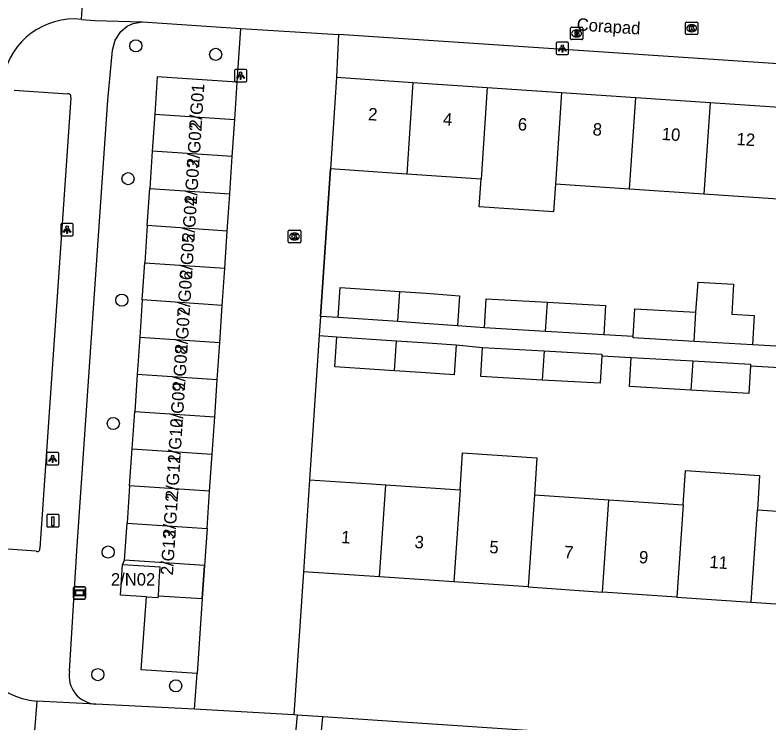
# Model space of a CAD drawing. Extents: x 161848 to 162726, y 385382 to 386521.
# Drawn here: x 162036.5 to 162097.2, y 385869.2 to 385926.3 of the extents above; entities that cross this region are included whole.
import ezdxf

# ---------------------------------------------------------------- set-up
doc = ezdxf.new("R2010")
doc.units = 0
for name, color, linetype in [('IMGEO_Boom', 7, 'Continuous'), ('IMGEO_Brandkraan', 7, 'Continuous'), ('IMGEO_Hek', 7, 'Continuous'), ('IMGEO_Kolk', 7, 'Continuous'), ('IMGEO_Laadpaal', 7, 'Continuous'), ('IMGEO_Lichtpunt', 7, 'Continuous'), ('IMGEO_Muur', 7, 'Continuous'), ('IMGEO_Openbare_ruimte_label', 7, 'Continuous'), ('IMGEO_Pand', 7, 'Continuous'), ('IMGEO_Pand_nummerreeks', 7, 'Continuous'), ('IMGEO_Parkeervlak_open', 7, 'Continuous'), ('IMGEO_Rijbaan_lokaal_open', 7, 'Continuous'), ('IMGEO_Verklikker', 7, 'Continuous'), ('IMGEO_Voetpad_open', 7, 'Continuous'), ('IMGEO_Woonerf_open', 7, 'Continuous')]:
    doc.layers.add(name, color=color, linetype=linetype)

msp = doc.modelspace()

# ---------------------------------------------------------------- linework, layer by layer
at = {"layer": 'IMGEO_Boom'}
for centre in [(162046.245, 385923.789), (162052.67, 385923.106), (162045.611, 385913.088), (162045.117, 385903.3), (162044.42, 385893.36), (162044.003, 385883.001), (162043.179, 385873.125), (162049.451, 385872.226)]:
    msp.add_circle(centre, 0.489, dxfattribs=at)
at = {"layer": 'IMGEO_Brandkraan'}
for p, q in [((162081.246, 385924.369), (162081.246, 385925.221)), ((162081.321, 385925.295), (162082.173, 385925.295)), ((162081.734, 385925.075), (162081.759, 385925.075)), ((162082.247, 385925.221), (162082.247, 385924.369)), ((162081.757, 385924.515), (162081.732, 385924.515)), ((162082.173, 385924.295), (162081.321, 385924.295))]:
    msp.add_line(p, q, dxfattribs=at)
for points in [[(162081.246, 385924.369), (162081.246, 385925.221)], [(162081.321, 385925.295), (162082.173, 385925.295)], [(162081.594, 385924.995), (162081.594, 385924.595), (162081.807, 385924.595)], [(162081.825, 385924.995), (162081.594, 385924.995)], [(162082.247, 385925.221), (162082.247, 385924.369)], [(162081.773, 385924.914), (162081.719, 385924.914), (162081.719, 385924.838)], [(162081.719, 385924.838), (162081.772, 385924.838)], [(162081.781, 385924.762), (162081.719, 385924.762), (162081.719, 385924.681)], [(162081.719, 385924.681), (162081.781, 385924.681)], [(162082.173, 385924.295), (162081.321, 385924.295)]]:
    msp.add_lwpolyline(points, dxfattribs=at)
for centre, radius, start, end in [((162081.323, 385925.219), 0.0765, 91.55205, 178.44795), ((162081.323, 385925.219), 0.0765, 91.55205, 178.44795), ((162081.829, 385924.85), 0.145, 59.4692, 91.53667), ((162082.171, 385925.219), 0.0765, 1.55205, 88.44795), ((162082.171, 385925.219), 0.0765, 1.55205, 88.44795), ((162081.774, 385924.876), 0.0379, 267.82845, 90.93552), ((162081.782, 385924.721), 0.0404, 269.87594, 90.50774), ((162081.813, 385924.846), 0.251, 268.66757, 293.53466), ((162081.854, 385924.897), 0.0922, 285.51372, 58.15012), ((162081.859, 385924.705), 0.105, 301.31148, 78.98903), ((162081.323, 385924.371), 0.0765, 181.55205, 268.44795), ((162081.323, 385924.371), 0.0765, 181.55205, 268.44795), ((162082.171, 385924.371), 0.0765, 271.55205, 358.44795), ((162082.171, 385924.371), 0.0765, 271.55205, 358.44795)]:
    msp.add_arc(centre, radius, start, end, dxfattribs=at)
for centre, major_axis, ratio, start_param, end_param in [((162081.733, 385924.795), (-0.387, 0.002), 0.722429, 4.712389, 7.853982), ((162081.758, 385924.795), (-0.39, 0.002), 0.717154, 1.570796, 4.712389)]:
    msp.add_ellipse(centre, major_axis=major_axis, ratio=ratio, start_param=start_param, end_param=end_param, dxfattribs=at)
at = {"layer": 'IMGEO_Hek'}
for points in [[(162051.593, 385879.249), (162051.781, 385881.906)], [(162048.052, 385879.467), (162051.593, 385879.249)]]:
    msp.add_lwpolyline(points, dxfattribs=at)
at = {"layer": 'IMGEO_Kolk'}
for p, q in [((162090.514, 385924.785), (162090.514, 385925.637)), ((162090.589, 385925.711), (162091.441, 385925.711)), ((162091.515, 385925.637), (162091.515, 385924.785)), ((162091.002, 385925.491), (162091.027, 385925.491)), ((162091.441, 385924.711), (162090.589, 385924.711)), ((162091.025, 385924.931), (162091, 385924.931)), ((162058.519, 385908.006), (162058.519, 385908.858)), ((162058.594, 385908.932), (162059.446, 385908.932)), ((162059.007, 385908.712), (162059.032, 385908.712)), ((162059.52, 385908.858), (162059.52, 385908.006)), ((162059.03, 385908.152), (162059.005, 385908.152)), ((162059.446, 385907.932), (162058.594, 385907.932))]:
    msp.add_line(p, q, dxfattribs=at)
for points in [[(162090.514, 385924.785), (162090.514, 385925.637)], [(162090.589, 385925.711), (162091.441, 385925.711)], [(162091.515, 385925.637), (162091.515, 385924.785)], [(162090.835, 385925.411), (162090.958, 385925.411), (162090.958, 385925.26), (162091.088, 385925.411), (162091.252, 385925.411), (162091.106, 385925.26), (162091.259, 385925.011), (162091.107, 385925.011), (162091.022, 385925.175), (162090.958, 385925.108), (162090.958, 385925.011), (162090.835, 385925.011), (162090.835, 385925.411)], [(162091.441, 385924.711), (162090.589, 385924.711)], [(162058.519, 385908.006), (162058.519, 385908.858)], [(162058.594, 385908.932), (162059.446, 385908.932)], [(162058.84, 385908.632), (162058.963, 385908.632), (162058.963, 385908.481), (162059.093, 385908.632), (162059.257, 385908.632), (162059.111, 385908.481), (162059.264, 385908.232), (162059.112, 385908.232), (162059.027, 385908.396), (162058.963, 385908.329), (162058.963, 385908.232), (162058.84, 385908.232), (162058.84, 385908.632)], [(162059.52, 385908.858), (162059.52, 385908.006)], [(162059.446, 385907.932), (162058.594, 385907.932)]]:
    msp.add_lwpolyline(points, dxfattribs=at)
for centre, start, end in [((162090.591, 385925.635), 91.55205, 178.44795), ((162090.591, 385925.635), 91.55205, 178.44795), ((162091.439, 385925.635), 1.55205, 88.44795), ((162091.439, 385925.635), 1.55205, 88.44795), ((162090.591, 385924.787), 181.55205, 268.44795), ((162090.591, 385924.787), 181.55205, 268.44795), ((162091.439, 385924.787), 271.55205, 358.44795), ((162091.439, 385924.787), 271.55205, 358.44795), ((162058.596, 385908.856), 91.55205, 178.44795), ((162058.596, 385908.856), 91.55205, 178.44795), ((162059.444, 385908.856), 1.55205, 88.44795), ((162059.444, 385908.856), 1.55205, 88.44795), ((162058.596, 385908.008), 181.55205, 268.44795), ((162058.596, 385908.008), 181.55205, 268.44795), ((162059.444, 385908.008), 271.55205, 358.44795), ((162059.444, 385908.008), 271.55205, 358.44795)]:
    msp.add_arc(centre, 0.0765, start, end, dxfattribs=at)
for centre, major_axis, ratio, start_param, end_param in [((162091.001, 385925.211), (-0.387, 0.002), 0.722429, 4.712389, 7.853982), ((162091.026, 385925.211), (-0.39, 0.002), 0.717154, 1.570796, 4.712389), ((162059.006, 385908.432), (-0.387, 0.002), 0.722429, 4.712389, 7.853982), ((162059.031, 385908.432), (-0.39, 0.002), 0.717154, 1.570796, 4.712389)]:
    msp.add_ellipse(centre, major_axis=major_axis, ratio=ratio, start_param=start_param, end_param=end_param, dxfattribs=at)
at = {"layer": 'IMGEO_Laadpaal'}
for p, q in [((162039.063, 385885.939), (162039.063, 385885.098)), ((162039.063, 385885.939), (162039.063, 385885.098)), ((162039.979, 385886.023), (162039.138, 385886.023)), ((162039.979, 385886.023), (162039.138, 385886.023)), ((162040.063, 385885.107), (162040.063, 385885.948)), ((162040.063, 385885.107), (162040.063, 385885.948)), ((162039.147, 385885.023), (162039.988, 385885.023)), ((162039.147, 385885.023), (162039.988, 385885.023))]:
    msp.add_line(p, q, dxfattribs=at)
msp.add_lwpolyline([(162039.478, 385885.836), (162039.638, 385885.836), (162039.638, 385885.103), (162039.478, 385885.103), (162039.478, 385885.836)], dxfattribs=at)
for centre, start, end in [((162039.141, 385885.945), 92.4484, 184.28452), ((162039.141, 385885.945), 92.4484, 184.28452), ((162039.985, 385885.945), 2.4484, 94.28452), ((162039.985, 385885.945), 2.4484, 94.28452), ((162039.141, 385885.101), 182.4484, 274.28452), ((162039.141, 385885.101), 182.4484, 274.28452), ((162039.985, 385885.101), 272.4484, 4.28452), ((162039.985, 385885.101), 272.4484, 4.28452)]:
    msp.add_arc(centre, 0.0779, start, end, dxfattribs=at)
at = {"layer": 'IMGEO_Lichtpunt'}
for p, q in [((162080.1, 385923.992), (162080.1, 385923.185)), ((162080.1, 385923.992), (162080.1, 385923.185)), ((162081.002, 385924.087), (162080.194, 385924.087)), ((162081.002, 385924.087), (162080.194, 385924.087)), ((162081.096, 385923.185), (162081.096, 385923.992)), ((162081.096, 385923.185), (162081.096, 385923.992)), ((162080.194, 385923.091), (162081.002, 385923.091)), ((162080.194, 385923.091), (162081.002, 385923.091)), ((162054.183, 385921.797), (162054.183, 385920.99)), ((162054.183, 385921.797), (162054.183, 385920.99)), ((162055.085, 385921.892), (162054.277, 385921.892)), ((162055.085, 385921.892), (162054.277, 385921.892)), ((162055.179, 385920.99), (162055.179, 385921.797)), ((162055.179, 385920.99), (162055.179, 385921.797)), ((162054.277, 385920.896), (162055.085, 385920.896)), ((162054.277, 385920.896), (162055.085, 385920.896)), ((162040.202, 385909.388), (162040.202, 385908.581)), ((162040.202, 385909.388), (162040.202, 385908.581)), ((162041.104, 385909.483), (162040.296, 385909.483)), ((162041.104, 385909.483), (162040.296, 385909.483)), ((162041.198, 385908.581), (162041.198, 385909.388)), ((162041.198, 385908.581), (162041.198, 385909.388)), ((162040.296, 385908.487), (162041.104, 385908.487)), ((162040.296, 385908.487), (162041.104, 385908.487)), ((162039.942, 385891.019), (162039.134, 385891.019)), ((162039.942, 385891.019), (162039.134, 385891.019)), ((162039.04, 385890.924), (162039.04, 385890.117)), ((162039.04, 385890.924), (162039.04, 385890.117)), ((162040.036, 385890.117), (162040.036, 385890.924)), ((162040.036, 385890.117), (162040.036, 385890.924)), ((162039.134, 385890.023), (162039.942, 385890.023)), ((162039.134, 385890.023), (162039.942, 385890.023))]:
    msp.add_line(p, q, dxfattribs=at)
for points in [[(162080.474, 385923.656), (162080.513, 385923.628), (162080.325, 385923.366), (162080.287, 385923.393), (162080.474, 385923.656)], [(162080.576, 385923.608), (162080.623, 385923.608), (162080.623, 385923.286), (162080.576, 385923.286), (162080.576, 385923.608)], [(162080.686, 385923.628), (162080.724, 385923.655), (162080.911, 385923.393), (162080.872, 385923.365), (162080.686, 385923.628)], [(162054.557, 385921.461), (162054.596, 385921.433), (162054.408, 385921.171), (162054.37, 385921.198), (162054.557, 385921.461)], [(162054.659, 385921.413), (162054.706, 385921.413), (162054.706, 385921.091), (162054.659, 385921.091), (162054.659, 385921.413)], [(162054.769, 385921.433), (162054.807, 385921.46), (162054.994, 385921.198), (162054.955, 385921.17), (162054.769, 385921.433)], [(162040.576, 385909.052), (162040.615, 385909.024), (162040.427, 385908.762), (162040.389, 385908.789), (162040.576, 385909.052)], [(162040.678, 385909.004), (162040.725, 385909.004), (162040.725, 385908.682), (162040.678, 385908.682), (162040.678, 385909.004)], [(162040.788, 385909.024), (162040.826, 385909.051), (162041.013, 385908.789), (162040.974, 385908.761), (162040.788, 385909.024)], [(162039.414, 385890.588), (162039.453, 385890.56), (162039.265, 385890.298), (162039.227, 385890.325), (162039.414, 385890.588)], [(162039.516, 385890.54), (162039.563, 385890.54), (162039.563, 385890.218), (162039.516, 385890.218), (162039.516, 385890.54)], [(162039.626, 385890.56), (162039.664, 385890.587), (162039.851, 385890.325), (162039.812, 385890.297), (162039.626, 385890.56)]]:
    msp.add_lwpolyline(points, dxfattribs=at)
for centre in [(162080.599, 385923.79), (162054.682, 385921.595), (162040.701, 385909.186), (162039.539, 385890.722)]:
    msp.add_circle(centre, 0.0994, dxfattribs=at)
for centre, start, end in [((162080.194, 385923.992), 90, 180), ((162080.194, 385923.992), 90, 180), ((162081.002, 385923.992), 0, 90), ((162081.002, 385923.992), 0, 90), ((162080.194, 385923.185), 180, 270), ((162080.194, 385923.185), 180, 270), ((162081.002, 385923.185), 270, 0), ((162081.002, 385923.185), 270, 360), ((162054.277, 385921.797), 90, 180), ((162054.277, 385921.797), 90, 180), ((162055.085, 385921.797), 0, 90), ((162055.085, 385921.797), 0, 90), ((162054.277, 385920.99), 180, 270), ((162054.277, 385920.99), 180, 270), ((162055.085, 385920.99), 270, 0), ((162055.085, 385920.99), 270, 360), ((162040.296, 385909.388), 90, 180), ((162040.296, 385909.388), 90, 180), ((162041.104, 385909.388), 0, 90), ((162041.104, 385909.388), 0, 90), ((162040.296, 385908.581), 180, 270), ((162040.296, 385908.581), 180, 270), ((162041.104, 385908.581), 270, 0), ((162041.104, 385908.581), 270, 360), ((162039.134, 385890.924), 90, 180), ((162039.134, 385890.924), 90, 180), ((162039.942, 385890.924), 0, 90), ((162039.942, 385890.924), 0, 90), ((162039.134, 385890.117), 180, 270), ((162039.134, 385890.117), 180, 270), ((162039.942, 385890.117), 270, 0), ((162039.942, 385890.117), 270, 360)]:
    msp.add_arc(centre, 0.0946, start, end, dxfattribs=at)
at = {"layer": 'IMGEO_Muur'}
for points in [[(162061.115, 385901.991), (162061.91, 385913.871)], [(162061.012, 385900.444), (162060.235, 385888.83)]]:
    msp.add_lwpolyline(points, dxfattribs=at)
at = {"layer": 'IMGEO_Pand'}
for points in [[(162054.41, 385920.859), (162047.964, 385921.294), (162047.762, 385918.298)], [(162054.208, 385917.863), (162054.41, 385920.859)], [(162062.409, 385921.268), (162061.91, 385913.871)], [(162062.409, 385921.268), (162068.56, 385920.853)], [(162068.56, 385920.853), (162068.06, 385913.456)], [(162068.56, 385920.853), (162074.547, 385920.449)], [(162074.547, 385920.449), (162074.047, 385913.052)], [(162074.547, 385920.449), (162080.533, 385920.045)], [(162080.533, 385920.045), (162080.033, 385912.648)], [(162080.533, 385920.045), (162086.52, 385919.641)], [(162086.02, 385912.244), (162086.52, 385919.641)], [(162086.52, 385919.641), (162092.506, 385919.236)], [(162092.506, 385919.236), (162092.006, 385911.84)], [(162092.506, 385919.236), (162098.492, 385918.832)], [(162047.762, 385918.298), (162047.56, 385915.301)], [(162047.762, 385918.298), (162054.208, 385917.863)], [(162054.006, 385914.866), (162054.208, 385917.863)], [(162047.56, 385915.301), (162047.357, 385912.305)], [(162054.006, 385914.866), (162047.56, 385915.301)], [(162053.803, 385911.87), (162054.006, 385914.866)], [(162068.06, 385913.456), (162066.899, 385913.534), (162061.91, 385913.871)], [(162074.047, 385913.052), (162068.06, 385913.456)], [(162080.033, 385912.648), (162079.884, 385910.429), (162073.897, 385910.834), (162074.047, 385913.052)], [(162047.155, 385909.309), (162047.357, 385912.305)], [(162047.357, 385912.305), (162053.803, 385911.87)], [(162086.02, 385912.244), (162080.033, 385912.648)], [(162092.006, 385911.84), (162086.02, 385912.244)], [(162053.601, 385908.873), (162053.803, 385911.87)], [(162097.992, 385911.436), (162092.006, 385911.84)], [(162047.155, 385909.309), (162046.953, 385906.312)], [(162053.601, 385908.873), (162047.155, 385909.309)], [(162053.399, 385905.877), (162053.601, 385908.873)], [(162046.751, 385903.316), (162046.953, 385906.312)], [(162046.953, 385906.312), (162053.399, 385905.877)], [(162053.197, 385902.881), (162053.399, 385905.877)], [(162091.363, 385902.329), (162091.527, 385904.756), (162094.38, 385904.595), (162094.243, 385902.166), (162096.053, 385902.064), (162095.92, 385899.71)], [(162062.543, 385901.895), (162062.706, 385904.319), (162067.507, 385903.995)], [(162067.343, 385901.571), (162067.507, 385903.995)], [(162067.507, 385903.995), (162069.631, 385903.852), (162072.304, 385903.662), (162072.138, 385901.245)], [(162046.751, 385903.316), (162046.548, 385900.319)], [(162053.197, 385902.881), (162046.751, 385903.316)], [(162074.33, 385901.063), (162074.463, 385903.417), (162079.39, 385903.138)], [(162079.231, 385900.785), (162079.39, 385903.138)], [(162079.39, 385903.138), (162084.08, 385902.873), (162083.947, 385900.519)], [(162052.994, 385899.884), (162053.197, 385902.881)], [(162086.31, 385900.385), (162086.436, 385902.608), (162091.363, 385902.329)], [(162091.204, 385899.976), (162091.363, 385902.329)], [(162067.343, 385901.571), (162062.543, 385901.895)], [(162072.138, 385901.245), (162069.465, 385901.428), (162067.343, 385901.571)], [(162079.231, 385900.785), (162074.33, 385901.063)], [(162083.947, 385900.519), (162079.231, 385900.785)], [(162046.548, 385900.319), (162046.346, 385897.323)], [(162046.548, 385900.319), (162052.994, 385899.884)], [(162067.075, 385897.61), (162062.271, 385897.934), (162062.434, 385900.348)], [(162062.434, 385900.348), (162067.238, 385900.023)], [(162091.204, 385899.976), (162086.303, 385900.254), (162086.31, 385900.385)], [(162052.792, 385896.888), (162052.994, 385899.884)], [(162067.075, 385897.61), (162067.238, 385900.023)], [(162072.034, 385899.699), (162071.871, 385897.286), (162069.196, 385897.467), (162067.075, 385897.61)], [(162067.238, 385900.023), (162069.36, 385899.88), (162072.034, 385899.699)], [(162078.974, 385896.864), (162074.039, 385897.143), (162074.172, 385899.497)], [(162074.172, 385899.497), (162079.132, 385899.216)], [(162095.92, 385899.71), (162091.204, 385899.976)], [(162079.132, 385899.216), (162078.974, 385896.864)], [(162079.132, 385899.216), (162083.789, 385898.953), (162083.782, 385898.822)], [(162083.782, 385898.822), (162083.656, 385896.599), (162078.974, 385896.864)], [(162090.947, 385896.055), (162086.012, 385896.334), (162086.145, 385898.688)], [(162086.145, 385898.688), (162091.106, 385898.407)], [(162091.106, 385898.407), (162090.947, 385896.055)], [(162091.106, 385898.407), (162095.762, 385898.144), (162095.755, 385898.014)], [(162095.755, 385898.014), (162095.629, 385895.79), (162090.947, 385896.055)], [(162046.346, 385897.323), (162046.144, 385894.327)], [(162052.792, 385896.888), (162046.346, 385897.323)], [(162052.59, 385893.892), (162052.792, 385896.888)], [(162045.942, 385891.33), (162046.144, 385894.327)], [(162046.144, 385894.327), (162052.59, 385893.892)], [(162052.388, 385890.895), (162052.59, 385893.892)], [(162045.739, 385888.334), (162045.942, 385891.33)], [(162045.942, 385891.33), (162052.388, 385890.895)], [(162072.363, 385888.013), (162072.565, 385891.006), (162078.551, 385890.602), (162078.349, 385887.609)], [(162052.185, 385887.899), (162052.388, 385890.895)], [(162090.322, 385886.799), (162090.507, 385889.565), (162096.492, 385889.161), (162096.308, 385886.395)], [(162060.235, 385888.83), (162059.734, 385881.408)], [(162060.235, 385888.83), (162065.224, 385888.493), (162066.376, 385888.417)], [(162045.739, 385888.334), (162045.537, 385885.337)], [(162052.185, 385887.899), (162045.739, 385888.334)], [(162065.875, 385880.994), (162066.376, 385888.417)], [(162066.376, 385888.417), (162072.363, 385888.013)], [(162072.363, 385888.013), (162071.862, 385880.59)], [(162051.983, 385884.902), (162052.185, 385887.899)], [(162078.349, 385887.609), (162077.848, 385880.186)], [(162078.349, 385887.609), (162084.336, 385887.204)], [(162083.835, 385879.781), (162084.336, 385887.204)], [(162084.336, 385887.204), (162090.322, 385886.799)], [(162090.322, 385886.799), (162089.821, 385879.377)], [(162095.807, 385878.973), (162096.308, 385886.395)], [(162096.308, 385886.395), (162102.295, 385885.991)], [(162045.335, 385882.341), (162045.537, 385885.337)], [(162045.537, 385885.337), (162051.983, 385884.902)], [(162051.983, 385884.902), (162051.781, 385881.906)], [(162047.093, 385879.396), (162045.014, 385879.525), (162045.166, 385881.962)], [(162048.052, 385879.467), (162048.153, 385881.095), (162048.195, 385881.774), (162045.166, 385881.962)], [(162051.781, 385881.906), (162045.335, 385882.341)], [(162065.875, 385880.994), (162059.734, 385881.408)], [(162071.862, 385880.59), (162065.875, 385880.994)], [(162077.848, 385880.186), (162071.862, 385880.59)], [(162077.848, 385880.186), (162083.835, 385879.781)], [(162047.093, 385879.396), (162048.044, 385879.337), (162048.052, 385879.467)], [(162089.821, 385879.377), (162083.835, 385879.781)], [(162089.821, 385879.377), (162095.807, 385878.973)], [(162095.807, 385878.973), (162101.794, 385878.569)]]:
    msp.add_lwpolyline(points, dxfattribs=at)
at = {"layer": 'IMGEO_Parkeervlak_open'}
msp.add_lwpolyline([(162051.166, 385873.202), (162046.678, 385873.52), (162047.093, 385879.396)], dxfattribs=at)
at = {"layer": 'IMGEO_Rijbaan_lokaal_open'}
for points in [[(162041.849, 385925.93), (162042.191, 385931.089)], [(162054.41, 385920.859), (162054.686, 385925.183)], [(162054.686, 385925.183), (162062.576, 385924.706)], [(162062.576, 385924.706), (162062.409, 385921.268)], [(162061.91, 385913.871), (162061.115, 385901.991)], [(162061.115, 385901.991), (162061.012, 385900.444)], [(162061.012, 385900.444), (162060.235, 385888.83)], [(162051.781, 385881.906), (162051.593, 385879.249)], [(162059.734, 385881.408), (162058.972, 385869.883)], [(162051.593, 385879.249), (162051.166, 385873.202)], [(162050.963, 385870.339), (162051.166, 385873.202)], [(162038.259, 385870.998), (162037.888, 385866.206)], [(162058.972, 385869.883), (162050.963, 385870.339)]]:
    msp.add_lwpolyline(points, dxfattribs=at)
for centre, radius, start, end in [((162041.277, 385920.133), 5.825, 84.36365, 168.49526), ((162038.751, 385877.016), 6.038, 177.64802, 265.3244)]:
    msp.add_arc(centre, radius, start, end, dxfattribs=at)
at = {"layer": 'IMGEO_Verklikker'}
for p, q in [((162041.204, 385879.312), (162041.204, 385880.112)), ((162041.204, 385880.112), (162041.204, 385879.312)), ((162041.304, 385880.212), (162042.094, 385880.212)), ((162042.094, 385880.212), (162041.304, 385880.212)), ((162042.194, 385880.112), (162042.194, 385879.312)), ((162042.194, 385879.312), (162042.194, 385880.112)), ((162042.094, 385879.212), (162041.304, 385879.212)), ((162041.304, 385879.212), (162042.094, 385879.212))]:
    msp.add_line(p, q, dxfattribs=at)
for points in [[(162041.305, 385879.944), (162042.093, 385879.944), (162042.093, 385879.48), (162041.305, 385879.48), (162041.305, 385879.944)], [(162041.37, 385879.879), (162041.37, 385879.545), (162042.028, 385879.545), (162042.028, 385879.879), (162041.37, 385879.879)]]:
    msp.add_lwpolyline(points, dxfattribs=at)
for centre, start, end in [((162041.304, 385880.112), 90, 180), ((162041.304, 385880.112), 90, 180), ((162042.094, 385880.112), 0, 90), ((162042.094, 385880.112), 360, 90), ((162041.304, 385879.312), 180, 270), ((162041.304, 385879.312), 180, 270), ((162042.094, 385879.312), 270, 0), ((162042.094, 385879.312), 270, 0)]:
    msp.add_arc(centre, 0.1, start, end, dxfattribs=at)
at = {"layer": 'IMGEO_Voetpad_open'}
for points in [[(162040.885, 385873.409), (162041.485, 385883.098), (162043.988, 385919.411), (162044.362, 385923.438), (162044.568, 385924.253), (162045.017, 385924.944), (162045.55, 385925.379), (162046.024, 385925.607), (162046.771, 385925.731)], [(162041.849, 385925.93), (162042.942, 385925.829), (162046.771, 385925.731)], [(162036.443, 385920.222), (162040.754, 385919.935)], [(162040.995, 385919.617), (162038.492, 385883.304)], [(162062.543, 385901.895), (162061.115, 385901.991)], [(162074.33, 385901.063), (162072.138, 385901.245)], [(162061.012, 385900.444), (162062.434, 385900.348)], [(162086.31, 385900.385), (162083.947, 385900.519)], [(162072.034, 385899.699), (162074.172, 385899.497)], [(162098.283, 385899.576), (162095.92, 385899.71)], [(162083.782, 385898.822), (162086.145, 385898.688)], [(162095.755, 385898.014), (162098.118, 385897.88)], [(162038.202, 385883.063), (162033.97, 385883.358)], [(162045.166, 385881.962), (162045.335, 385882.341)], [(162048.052, 385879.467), (162051.593, 385879.249)], [(162043.014, 385870.751), (162038.259, 385870.998)]]:
    msp.add_lwpolyline(points, dxfattribs=at)
for centre, radius, start, end in [((162040.776, 385919.701), 0.235, 338.97488, 95.33931), ((162038.307, 385883.232), 0.199, 238.12783, 21.32767), ((162043.156, 385873.047), 2.3, 170.9383, 266.44963)]:
    msp.add_arc(centre, radius, start, end, dxfattribs=at)
at = {"layer": 'IMGEO_Woonerf_open'}
for points in [[(162046.771, 385925.731), (162054.686, 385925.183)], [(162110.864, 385921.497), (162062.576, 385924.706)], [(162050.963, 385870.339), (162043.014, 385870.751)], [(162059.222, 385869.866), (162058.738, 385864.808)], [(162059.222, 385869.866), (162058.972, 385869.883)], [(162061.295, 385869.726), (162059.222, 385869.866)], [(162060.825, 385864.668), (162061.295, 385869.726)], [(162085.397, 385868.102), (162061.295, 385869.726)]]:
    msp.add_lwpolyline(points, dxfattribs=at)

# ---------------------------------------------------------------- texts
at = {"layer": 'IMGEO_Openbare_ruimte_label'}
msp.add_text('Corapad', height=1, rotation=356.21641, dxfattribs=at).set_placement((162081.732, 385925.039))
at = {"layer": 'IMGEO_Pand_nummerreeks'}
for s, rotation, p in [('2/G01', 86.3283, (162051.534, 385917.088)), ('2', 356.13846, (162064.926, 385917.811)), ('4', 356.13846, (162070.956, 385917.404)), ('6', 356.13846, (162076.983, 385916.997)), ('2/G02', 86.3283, (162051.334, 385913.974)), ('8', 356.13846, (162083.015, 385916.59)), ('10', 356.13846, (162088.583, 385916.214)), ('12', 356.13846, (162094.605, 385915.808)), ('2/G03', 86.3283, (162051.142, 385910.984)), ('2/G04', 86.3283, (162050.95, 385907.987)), ('2/G05', 86.3283, (162050.758, 385904.99)), ('2/G06', 86.3283, (162050.566, 385901.994)), ('2/G07', 86.3283, (162050.373, 385898.997)), ('2/G08', 86.3283, (162050.181, 385896.003)), ('2/G09', 86.3283, (162049.988, 385893)), ('2/G10', 86.3283, (162049.802, 385890.101)), ('2/G11', 86.3283, (162049.617, 385887.211)), ('2/G12', 86.3283, (162049.417, 385884.098)), ('2/G13', 86.3283, (162049.225, 385881.107)), ('1', 356.13906, (162062.755, 385883.73)), ('3', 356.13906, (162068.667, 385883.331)), ('5', 356.13906, (162074.692, 385882.925)), ('7', 356.13906, (162080.717, 385882.518)), ('9', 356.13906, (162086.742, 385882.112)), ('11', 356.13906, (162092.422, 385881.728))]:
    msp.add_text(s, height=1, rotation=rotation, dxfattribs=at).set_placement(p)
msp.add_text('2/N02', height=1, dxfattribs=at).set_placement((162044.233, 385880.303))

doc.saveas('drawing.dxf')
